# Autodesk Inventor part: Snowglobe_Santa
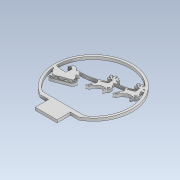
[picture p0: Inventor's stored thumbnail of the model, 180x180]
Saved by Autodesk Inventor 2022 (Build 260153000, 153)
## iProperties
Created: 2021-12
Part Number: Snowglobe_Santa
Material: Generic
Document SubType Name: Modeling
Designer: allis
Density: 1 g/cm^3
Appearance: Default
Author: allis
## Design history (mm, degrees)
sketch "Sketch5"
  geometry: L1 (55.829, -34.486)-(55.367, -34.264); L2 (55.367, -34.264)-(54.988, -33.966); L3 (54.988, -33.966)-(54.458, -34.133); L4 (54.458, -34.133)-(54.922, -34.727); L5 (54.922, -34.727)-(55.205, -34.805); L6 (55.205, -34.805)-(55.829, -34.486); L7 (78.314, -26.962)-(78.691, -27.54); L8 (78.691, -27.54)-(79.082, -27.643); L9 (79.082, -27.643)-(79.572, -27.293); L10 (79.572, -27.293)-(78.981, -26.9); L11 (78.981, -26.9)-(78.72, -26.832); L12 (78.72, -26.832)-(78.314, -26.962); L13 (84.482, -26.831)-(84.511, -26.776); L14 (84.511, -26.776)-(84.539, -26.722); L15 (84.539, -26.722)-(84.568, -26.667); L16 (84.568, -26.667)-(84.405, -26.479); L17 (84.405, -26.479)-(84.261, -26.27); L18 (84.261, -26.27)-(84.075, -26.109); L19 (84.075, -26.109)-(83.806, -25.878); L20 (83.806, -25.878)-(83.519, -25.661); L21 (83.519, -25.661)-(83.215, -25.48); L22 (83.215, -25.48)-(83.027, -25.369); L23 (83.027, -25.369)-(82.794, -25.296); L24 (82.794, -25.296)-(82.578, -25.286); L25 (82.578, -25.286)-(82.481, -25.281); L26 (82.481, -25.281)-(82.313, -25.463); L27 (82.313, -25.463)-(82.291, -25.582); L28 (82.291, -25.582)-(82.27, -25.696); L29 (82.27, -25.696)-(82.36, -25.91); L30 (82.36, -25.91)-(82.459, -25.956); L31 (82.459, -25.956)-(83.125, -26.267); L32 (83.125, -26.267)-(83.806, -26.544); L33 (83.806, -26.544)-(84.482, -26.831); L34 (56.351, -38.195)-(54.196, -39.91); L35 (54.196, -39.91)-(51.899, -41.152); L36 (51.899, -41.152)-(49.497, -42.223); L37 (49.497, -42.223)-(49.619, -42.235); L38 (49.619, -42.235)-(49.722, -42.209); L39 (49.722, -42.209)-(49.823, -42.175); L40 (49.823, -42.175)-(50.53, -41.943); L41 (50.53, -41.943)-(51.226, -41.672); L42 (51.226, -41.672)-(51.944, -41.483); L43 (51.944, -41.483)-(53.069, -41.188); L44 (53.069, -41.188)-(54.136, -40.764); L45 (54.136, -40.764)-(55.142, -40.188); L46 (55.142, -40.188)-(55.856, -39.779); L47 (55.856, -39.779)-(56.291, -39.178); L48 (56.291, -39.178)-(56.351, -38.195); L49 (19.909, -66.328)-(21.073, -65.887); L50 (21.073, -65.887)-(22.169, -65.471); L51 (22.169, -65.471)-(23.337, -65.029); L52 (23.337, -65.029)-(22.285, -64.01); L53 (22.285, -64.01)-(21.286, -63.043); L54 (21.286, -63.043)-(20.212, -62.003); L55 (20.212, -62.003)-(20.107, -63.497); L56 (20.107, -63.497)-(20.011, -64.867); L57 (20.011, -64.867)-(19.909, -66.328); L58 (28.399, -58.962)-(28.294, -60.432); L59 (28.294, -60.432)-(28.197, -61.799); L60 (28.197, -61.799)-(28.095, -63.236); L61 (28.095, -63.236)-(29.266, -62.789); L62 (29.266, -62.789)-(30.38, -62.363); L63 (30.38, -62.363)-(31.563, -61.911); L64 (31.563, -61.911)-(30.49, -60.911)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; 1 further point
  constraints: 20 other
extrude "Extrusion5" new body sketch "Sketch5" distance "d9" = 3.175; taper "d10" = 0 deg
body "Solid5"
